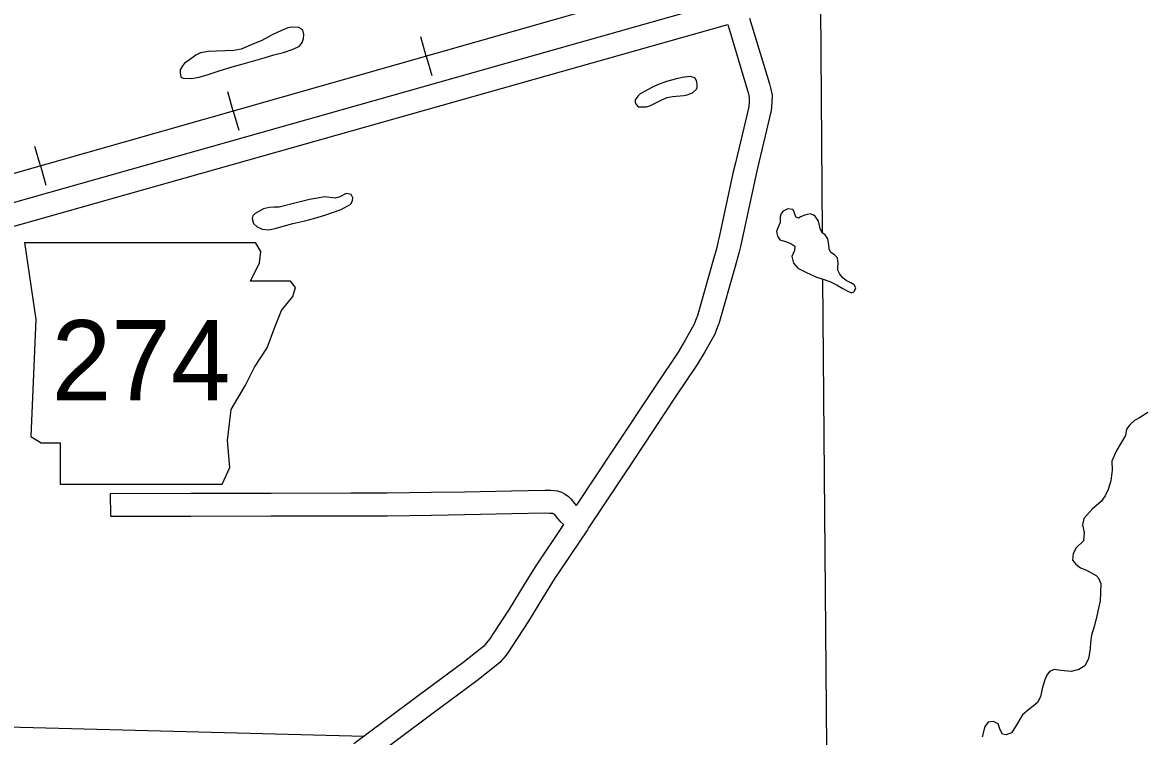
# Model space of a CAD drawing. Extents: x 1373094 to 1376427, y 1168361 to 1170494.
# Drawn here: x 1373679.1 to 1373802.5, y 1169997.1 to 1170075.4 of the extents above; entities that cross this region are included whole.
import ezdxf

# ---------------------------------------------------------------- set-up
doc = ezdxf.new("R2010")
doc.units = 0
doc.layers.add('R_Axis', color=7, linetype='Continuous')

msp = doc.modelspace()

# ---------------------------------------------------------------- linework, layer by layer
at = {"layer": 'R_Axis'}
for p, q in [((1373723.38, 1170071.71), (1373722.77, 1170073.83)), ((1373723.38, 1170071.71), (1373723.98, 1170069.6)), ((1373702.21, 1170065.69), (1373701.61, 1170067.81)), ((1373702.21, 1170065.69), (1373702.82, 1170063.58)), ((1373681.05, 1170059.68), (1373680.45, 1170061.79)), ((1373681.05, 1170059.68), (1373681.65, 1170057.56)), ((1373679.28, 1170051.27), (1373680.55, 1170042.81)), ((1373705.22, 1170050.29), (1373704.64, 1170051.26)), ((1373705.08, 1170049.02), (1373705.22, 1170050.29)), ((1373704.1, 1170047.04), (1373705.08, 1170049.02)), ((1373708.47, 1170047.04), (1373704.1, 1170047.04)), ((1373709.03, 1170046.34), (1373708.47, 1170047.04)), ((1373707.48, 1170043.8), (1373708.75, 1170045.35)), ((1373708.75, 1170045.35), (1373709.03, 1170046.34)), ((1373680.55, 1170042.81), (1373679.99, 1170029.98)), ((1373706.78, 1170041.97), (1373707.48, 1170043.8)), ((1373705.93, 1170039.71), (1373706.78, 1170041.97)), ((1373704.52, 1170037.6), (1373705.93, 1170039.71)), ((1373703.53, 1170035.62), (1373704.52, 1170037.6)), ((1373701.98, 1170032.94), (1373703.53, 1170035.62)), ((1373701.56, 1170029.56), (1373701.98, 1170032.94)), ((1373679.99, 1170029.98), (1373681.12, 1170029.28)), ((1373681.12, 1170029.28), (1373683.23, 1170029.28)), ((1373683.23, 1170029.28), (1373683.23, 1170024.77)), ((1373701.84, 1170026.6), (1373701.56, 1170029.56)), ((1373701, 1170024.77), (1373701.84, 1170026.6)), ((1373683.23, 1170024.77), (1373701, 1170024.77)), ((1373688.76, 1170021.25), (1373688.75, 1170023.75))]:
    msp.add_line(p, q, dxfattribs=at)
for points in [[(1373755.25, 1170077.44), (1373631.72, 1170042.54)], [(1373591.87, 1170034.32), (1373741.71, 1170076.93)], [(1373591.87, 1170034.32), (1373741.71, 1170076.93)], [(1373766.63, 1170077.03), (1373766.83, 1170052.35)], [(1373577.78, 1170024.53), (1373630.86, 1170039.7), (1373756.46, 1170075.18)], [(1373708.18, 1170074.82), (1373707.15, 1170074.37), (1373706.49, 1170074.03), (1373705.33, 1170073.41), (1373704.36, 1170073.02), (1373703.08, 1170072.46), (1373702.25, 1170072.33), (1373700.36, 1170072.26), (1373699.48, 1170072.23), (1373698.62, 1170072.09), (1373698.09, 1170071.81), (1373697.25, 1170071.21), (1373696.85, 1170070.95), (1373696.63, 1170070.63), (1373696.39, 1170070.22), (1373696.37, 1170069.89), (1373696.47, 1170069.4), (1373696.7, 1170069.31), (1373697.62, 1170069.24), (1373698.45, 1170069.4), (1373699.44, 1170069.71), (1373700.75, 1170070.14), (1373702.07, 1170070.53), (1373703.3, 1170070.85), (1373704.33, 1170071.15), (1373705.6, 1170071.52), (1373706.67, 1170071.85), (1373707.7, 1170072.12), (1373708.79, 1170072.48), (1373709.46, 1170072.8), (1373709.76, 1170073.2), (1373709.91, 1170073.64), (1373709.93, 1170074.09), (1373709.82, 1170074.57), (1373709.4, 1170074.87), (1373708.63, 1170074.9), (1373708.18, 1170074.82)], [(1373756.46, 1170075.18), (1373758.63, 1170067.94)], [(1373758.86, 1170075.87), (1373761.03, 1170068.66)], [(1373749.73, 1170068.93), (1373748.75, 1170068.57), (1373748.19, 1170068.32), (1373747.32, 1170067.83), (1373746.86, 1170067.57), (1373746.59, 1170067.32), (1373746.3, 1170066.93), (1373746.29, 1170066.65), (1373746.4, 1170066.4), (1373746.64, 1170066.14), (1373747.55, 1170066.15), (1373748, 1170066.28), (1373749.23, 1170066.9), (1373749.82, 1170067.17), (1373750.4, 1170067.29), (1373751.64, 1170067.38), (1373752.02, 1170067.45), (1373752.6, 1170067.67), (1373753.05, 1170068.09), (1373753.11, 1170068.27), (1373753.12, 1170068.59), (1373753.04, 1170069.04), (1373752.86, 1170069.33), (1373752.33, 1170069.48), (1373751.45, 1170069.36), (1373750.69, 1170069.2), (1373749.73, 1170068.93)], [(1373761.03, 1170068.66), (1373761.16, 1170068.23), (1373761.34, 1170067.44), (1373761.31, 1170066.57), (1373761.24, 1170065.76), (1373759.73, 1170059.42)], [(1373758.63, 1170067.94), (1373758.74, 1170067.59), (1373758.83, 1170067.19), (1373758.82, 1170066.72), (1373758.77, 1170066.16), (1373757.3, 1170060)], [(1373757.3, 1170060), (1373757.06, 1170059.01), (1373755.48, 1170051.69), (1373755.41, 1170051.4)], [(1373759.73, 1170059.42), (1373759.5, 1170058.45), (1373757.92, 1170051.15), (1373757.85, 1170050.84)], [(1373709.27, 1170055.64), (1373707.24, 1170055.13), (1373706.71, 1170055.16), (1373706.13, 1170055.11), (1373705.53, 1170054.96), (1373704.6, 1170054.43), (1373704.36, 1170054.2), (1373704.28, 1170053.89), (1373704.42, 1170053.35), (1373704.81, 1170052.97), (1373705.37, 1170052.72), (1373706.07, 1170052.64), (1373706.81, 1170052.79), (1373707.69, 1170053.05), (1373708.73, 1170053.34), (1373710.06, 1170053.64), (1373711.17, 1170053.94), (1373712.24, 1170054.28), (1373714.03, 1170054.9), (1373715.1, 1170055.48), (1373715.29, 1170055.87), (1373715.34, 1170056.16), (1373715.15, 1170056.54), (1373714.58, 1170056.65), (1373713.88, 1170056.28), (1373713.43, 1170056.13), (1373712.21, 1170056.28), (1373711.45, 1170056.14), (1373710.58, 1170055.98), (1373709.27, 1170055.64)], [(1373764.91, 1170054.27), (1373764.45, 1170054.07), (1373764.26, 1170053.93), (1373763.97, 1170054.01), (1373763.83, 1170054.37), (1373763.74, 1170054.64), (1373763.6, 1170054.87), (1373763.05, 1170054.95), (1373762.56, 1170054.7), (1373762.31, 1170054.46), (1373762.21, 1170054.04), (1373762.23, 1170053.47), (1373761.96, 1170052.88), (1373761.82, 1170052.48), (1373761.91, 1170051.96), (1373762.17, 1170051.57), (1373762.81, 1170051.37), (1373763.38, 1170051.17), (1373763.82, 1170050.88), (1373763.8, 1170050.38), (1373763.5, 1170049.74), (1373763.68, 1170048.99), (1373764.14, 1170048.45), (1373765.02, 1170048.01), (1373766.2, 1170047.45), (1373767.04, 1170047.19), (1373767.75, 1170046.96), (1373768.47, 1170046.57), (1373769.08, 1170046.23), (1373769.62, 1170045.92), (1373770.03, 1170045.76), (1373770.29, 1170045.85), (1373770.37, 1170045.92), (1373770.42, 1170046.02), (1373770.53, 1170046.28), (1373770.35, 1170046.62), (1373769.95, 1170046.83), (1373769.47, 1170047.1), (1373769.1, 1170047.39), (1373768.75, 1170047.81), (1373768.54, 1170048.24), (1373768.53, 1170048.54), (1373768.58, 1170048.97), (1373768.5, 1170049.57), (1373768.17, 1170049.9), (1373767.78, 1170050.17), (1373767.59, 1170050.58), (1373767.54, 1170051.06), (1373767.44, 1170051.66), (1373767.14, 1170052.09), (1373766.87, 1170052.28), (1373766.62, 1170052.75), (1373766.53, 1170053.14), (1373766.41, 1170053.62), (1373766.05, 1170054.16), (1373765.88, 1170054.25), (1373765.53, 1170054.41), (1373765.23, 1170054.35), (1373764.91, 1170054.27)], [(1373755.41, 1170051.4), (1373755.25, 1170050.71), (1373754.86, 1170049.32), (1373753.1, 1170043.12), (1373753.08, 1170043.09)], [(1373679.28, 1170051.27), (1373704.64, 1170051.26)], [(1373757.85, 1170050.84), (1373757.68, 1170050.08), (1373757.26, 1170048.63), (1373755.47, 1170042.33), (1373755.42, 1170042.2)], [(1373766.87, 1170047.24), (1373767.3, 1169995.84), (1373768.53, 1169951.5), (1373767.68, 1169907.82), (1373767.62, 1169893.28)], [(1373753.08, 1170043.09), (1373752.75, 1170042.22), (1373751.79, 1170040.55), (1373751.01, 1170039.24), (1373748.7, 1170035.81)], [(1373755.42, 1170042.2), (1373755.01, 1170041.15), (1373753.95, 1170039.28), (1373753.12, 1170037.9), (1373750.78, 1170034.42)], [(1373748.7, 1170035.81), (1373748.7, 1170035.81), (1373743.84, 1170028.47)], [(1373750.78, 1170034.42), (1373750.78, 1170034.42), (1373745.92, 1170027.09)], [(1373802.57, 1170032.62), (1373801.64, 1170032.04), (1373801.1, 1170031.74), (1373800.59, 1170031.26), (1373800.23, 1170030.78), (1373800.12, 1170030.11), (1373799.55, 1170029.18), (1373799.08, 1170028.38), (1373798.61, 1170027.28), (1373798.64, 1170026.29), (1373798.49, 1170025.12), (1373798.19, 1170024.16), (1373797.89, 1170023.48), (1373797.43, 1170022.87), (1373796.5, 1170022.04), (1373795.52, 1170020.99), (1373795.38, 1170020.3), (1373795.57, 1170019.45), (1373795.51, 1170018.53), (1373794.69, 1170017.78), (1373794.36, 1170017.15), (1373794.29, 1170016.43), (1373794.64, 1170015.99), (1373795.18, 1170015.57), (1373795.82, 1170015.31), (1373796.87, 1170014.74), (1373797.1, 1170014.51), (1373797.38, 1170013.85), (1373797.36, 1170012.85), (1373797.31, 1170011.96), (1373797.15, 1170011.15), (1373796.96, 1170010.31), (1373796.7, 1170009.27), (1373796.39, 1170008.18), (1373796.25, 1170007.39), (1373796.22, 1170006.74), (1373796.03, 1170005.58), (1373795.66, 1170004.82), (1373794.97, 1170004.44), (1373794.16, 1170004.22), (1373793.01, 1170004.32), (1373792.29, 1170004.41), (1373791.77, 1170004.2), (1373791.48, 1170003.8), (1373791.25, 1170003.28), (1373790.97, 1170002.34), (1373790.77, 1170001.43), (1373790.44, 1170000.82), (1373789.98, 1170000.42), (1373789.51, 1170000.05), (1373788.8, 1169999.45), (1373788.01, 1169998.09), (1373787.58, 1169997.47), (1373787, 1169997.26), (1373786.62, 1169997.33), (1373786.35, 1169997.79), (1373786.13, 1169998.48), (1373785.63, 1169998.73), (1373785.05, 1169998.65), (1373784.66, 1169998.19), (1373784.38, 1169997.04)], [(1373743.84, 1170028.47), (1373739.83, 1170022.42)], [(1373745.92, 1170027.09), (1373741.2, 1170019.95), (1373741.06, 1170019.74)], [(1373688.75, 1170023.75), (1373697.55, 1170023.76)], [(1373697.55, 1170023.76), (1373706.35, 1170023.78)], [(1373706.35, 1170023.78), (1373715.15, 1170023.79)], [(1373715.15, 1170023.79), (1373719.08, 1170023.8), (1373723.94, 1170023.87)], [(1373723.94, 1170023.87), (1373727.58, 1170023.92), (1373732.73, 1170024.03)], [(1373732.73, 1170024.03), (1373736.4, 1170024.1), (1373737.01, 1170024.09), (1373737.44, 1170024.06), (1373737.79, 1170024.01), (1373738.22, 1170023.87), (1373738.64, 1170023.67), (1373738.99, 1170023.4), (1373739.25, 1170023.14), (1373739.83, 1170022.42)], [(1373688.76, 1170021.25), (1373697.56, 1170021.26)], [(1373697.56, 1170021.26), (1373706.36, 1170021.28)], [(1373706.36, 1170021.28), (1373715.16, 1170021.29)], [(1373715.16, 1170021.29), (1373719.1, 1170021.3), (1373723.97, 1170021.37)], [(1373723.97, 1170021.37), (1373727.63, 1170021.42), (1373732.78, 1170021.53)], [(1373732.78, 1170021.53), (1373736.39, 1170021.6), (1373736.89, 1170021.59), (1373737.19, 1170021.57), (1373737.24, 1170021.56), (1373737.27, 1170021.55), (1373737.3, 1170021.54), (1373737.35, 1170021.5), (1373737.41, 1170021.45), (1373737.78, 1170020.99), (1373738.04, 1170020.7), (1373738.44, 1170020.33)], [(1373738.44, 1170020.33), (1373735.32, 1170015.7), (1373734.12, 1170013.75)], [(1373741.06, 1170019.74), (1373737.42, 1170014.35), (1373736.25, 1170012.44)], [(1373734.12, 1170013.75), (1373732.47, 1170011.06), (1373730.74, 1170008.38), (1373730.34, 1170007.8), (1373730.14, 1170007.52), (1373729.7, 1170006.98), (1373729.49, 1170006.81)], [(1373736.25, 1170012.44), (1373734.59, 1170009.73), (1373732.82, 1170006.99), (1373732.39, 1170006.38), (1373732.14, 1170006.01), (1373731.46, 1170005.18), (1373731.04, 1170004.85)], [(1373729.49, 1170006.81), (1373727.4, 1170005.16), (1373722.5, 1170001.52)], [(1373731.04, 1170004.85), (1373728.92, 1170003.18), (1373724, 1169999.51)], [(1373722.5, 1170001.52), (1373718.89, 1169998.82), (1373715.45, 1169996.26)], [(1373724, 1169999.51), (1373720.38, 1169996.82), (1373716.94, 1169994.25)], [(1373586.29, 1169998.87), (1373589.64, 1169998.89), (1373678.87, 1169998.09), (1373716.62, 1169997.13)]]:
    msp.add_lwpolyline(points, dxfattribs=at)

# ---------------------------------------------------------------- texts
msp.add_text('274', height=8.8, dxfattribs=at).set_placement((1373682.27, 1170033.95))

doc.saveas('drawing.dxf')
